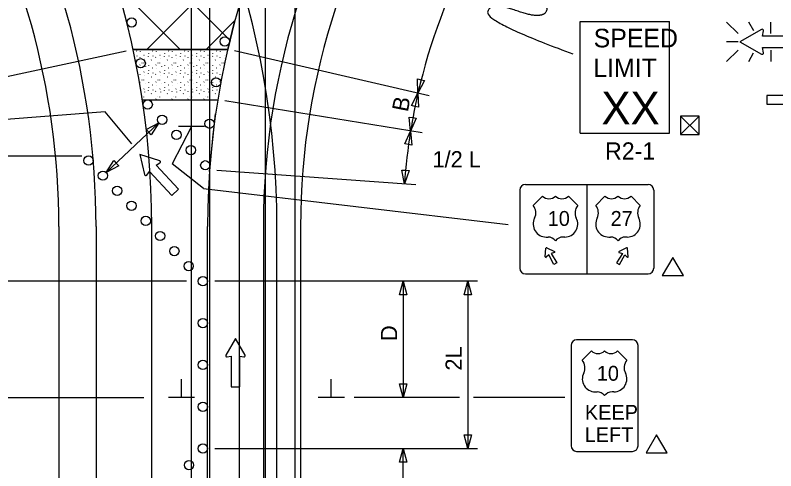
# Model space of a CAD drawing. Extents: x 16452 to 19508, y 5713 to 7079.
# Drawn here: x 16897.2 to 17224.3, y 6278.6 to 6474.6 of the extents above; entities that cross this region are included whole.
import ezdxf

# ---------------------------------------------------------------- set-up
doc = ezdxf.new("R2010")
doc.units = 0
for name, color, linetype in [('ALI_LEGAL_EX', 7, 'Continuous'), ('MT_SCRATCH_LEVEL_A', 7, 'Continuous'), ('MT_SCRATCH_LEVEL_E', 7, 'Continuous'), ('PAVT_EDGE_EX', 7, 'Continuous'), ('TRAFFIC_SIGNS_PR', 7, 'Continuous'), ('TYPICAL_EX', 7, 'Continuous'), ('TYPICAL_TEXT_DIMEN_PR', 7, 'Continuous')]:
    doc.layers.add(name, color=color, linetype=linetype)

msp = doc.modelspace()

# ---------------------------------------------------------------- linework, layer by layer
at = {"layer": 'ALI_LEGAL_EX'}
for p, q in [((16980.68, 6974.12), (16980.68, 6155.98)), ((17004.68, 6974.12), (17004.68, 6155.98)), ((16980.68, 6877.04), (16980.68, 6013.12)), ((17004.68, 6877.04), (17004.68, 6013.12)), ((16973.01, 6139.03), (16973.01, 6639.38)), ((16993.65, 6024.8), (16993.65, 6525.15)), ((17017.65, 6024.8), (17017.65, 6525.15)), ((16955.93, 6107.09), (16955.93, 6383.76)), ((16979.93, 6107.09), (16979.93, 6383.76)), ((17009.75, 5773.57), (17009.75, 6383.76))]:
    msp.add_line(p, q, dxfattribs=at)
for points in [[(16980.7, 6407.3), (16983.32, 6432.16)], [(16955.93, 6307.09), (16955.93, 6332.09)], [(16979.93, 6307.09), (16979.93, 6332.09)]]:
    msp.add_lwpolyline(points, dxfattribs=at)
for centre, radius, start, end in [((16591.93, 6383.76), 364, 0, 40.1909), ((16645.75, 6383.76), 364, 0, 40.1909), ((17319.93, 6383.76), 340, 137.516, 180)]:
    msp.add_arc(centre, radius, start, end, dxfattribs=at)
at = {"layer": 'MT_SCRATCH_LEVEL_A'}
for p, q in [((16953.81, 6459.9), (17004.45, 6510.55)), ((16968.1, 6459.9), (16940.97, 6487.03)), ((16989.56, 6463.9), (16969.88, 6483.58)), ((16979.27, 6459.9), (16991.66, 6472.3)), ((16991.51, 6471.74), (16988.57, 6459.9)), ((16947.88, 6459.9), (16988.57, 6459.9)), ((16947.88, 6459.9), (16988.57, 6459.9)), ((16988.57, 6459.9), (16947.88, 6459.9)), ((16949.38, 6459.26), (16949.43, 6459.18)), ((16950.91, 6459.12), (16950.96, 6459.04)), ((16953.22, 6459.9), (16953.25, 6459.86)), ((16956.26, 6459.26), (16956.31, 6459.18)), ((16957.79, 6459.12), (16957.85, 6459.04)), ((16960.1, 6459.9), (16960.14, 6459.86)), ((16963.15, 6459.26), (16963.2, 6459.18)), ((16964.68, 6459.12), (16964.73, 6459.04)), ((16966.99, 6459.9), (16967.02, 6459.86)), ((16970.04, 6459.26), (16970.09, 6459.18)), ((16971.57, 6459.12), (16971.62, 6459.04)), ((16973.88, 6459.9), (16973.91, 6459.86)), ((16976.93, 6459.26), (16976.98, 6459.18)), ((16978.46, 6459.12), (16978.51, 6459.04)), ((16980.77, 6459.9), (16980.8, 6459.86)), ((16983.81, 6459.26), (16983.87, 6459.18)), ((16985.34, 6459.12), (16985.4, 6459.04)), ((16987.65, 6459.9), (16987.69, 6459.86)), ((16948.81, 6455.3), (16948.86, 6455.41)), ((16949.42, 6457.05), (16949.48, 6456.97)), ((16950.71, 6456.47), (16950.72, 6456.36)), ((16952.55, 6457.33), (16952.6, 6457.44)), ((16952.74, 6456.13), (16952.79, 6456.05)), ((16954.47, 6458.2), (16954.53, 6458.12)), ((16954.52, 6456.8), (16954.57, 6456.91)), ((16955.69, 6455.3), (16955.75, 6455.41)), ((16956.31, 6457.05), (16956.36, 6456.97)), ((16957.59, 6456.47), (16957.61, 6456.36)), ((16959.44, 6457.33), (16959.49, 6457.44)), ((16959.62, 6456.13), (16959.67, 6456.05)), ((16961.36, 6458.2), (16961.41, 6458.12)), ((16961.4, 6456.8), (16961.46, 6456.91)), ((16962.58, 6455.3), (16962.63, 6455.41)), ((16963.2, 6457.05), (16963.25, 6456.97)), ((16964.48, 6456.47), (16964.49, 6456.36)), ((16966.32, 6457.33), (16966.37, 6457.44)), ((16966.51, 6456.13), (16966.56, 6456.05)), ((16968.25, 6458.2), (16968.3, 6458.12)), ((16968.29, 6456.8), (16968.34, 6456.91)), ((16969.47, 6455.3), (16969.52, 6455.41)), ((16970.09, 6457.05), (16970.14, 6456.97)), ((16971.37, 6456.47), (16971.38, 6456.36)), ((16973.21, 6457.33), (16973.26, 6457.44)), ((16973.4, 6456.13), (16973.45, 6456.05)), ((16975.14, 6458.2), (16975.19, 6458.12)), ((16975.18, 6456.8), (16975.23, 6456.91)), ((16976.36, 6455.3), (16976.41, 6455.41)), ((16976.97, 6457.05), (16977.03, 6456.97)), ((16978.26, 6456.47), (16978.27, 6456.36)), ((16980.1, 6457.33), (16980.15, 6457.44)), ((16980.29, 6456.13), (16980.34, 6456.05)), ((16982.02, 6458.2), (16982.08, 6458.12)), ((16982.07, 6456.8), (16982.12, 6456.91)), ((16983.24, 6455.3), (16983.3, 6455.41)), ((16983.86, 6457.05), (16983.91, 6456.97)), ((16985.14, 6456.47), (16985.16, 6456.36)), ((16986.99, 6457.33), (16987.04, 6457.44)), ((16987.17, 6456.13), (16987.22, 6456.05)), ((16950.83, 6453.1), (16950.88, 6453.22)), ((16951.59, 6454.06), (16951.64, 6453.98)), ((16952.33, 6454.03), (16952.38, 6453.95)), ((16953.2, 6452.65), (16953.25, 6452.57)), ((16954.65, 6452.8), (16954.7, 6452.92)), ((16956.26, 6451.97), (16956.31, 6451.9)), ((16957.71, 6453.1), (16957.76, 6453.22)), ((16958.48, 6454.06), (16958.53, 6453.98)), ((16959.22, 6454.03), (16959.27, 6453.95)), ((16960.08, 6452.65), (16960.14, 6452.57)), ((16961.53, 6452.8), (16961.58, 6452.92)), ((16963.15, 6451.97), (16963.2, 6451.9)), ((16964.6, 6453.1), (16964.65, 6453.22)), ((16965.37, 6454.06), (16965.42, 6453.98)), ((16966.1, 6454.03), (16966.15, 6453.95)), ((16966.97, 6452.65), (16967.02, 6452.57)), ((16968.42, 6452.8), (16968.47, 6452.92)), ((16970.04, 6451.97), (16970.09, 6451.9)), ((16971.49, 6453.1), (16971.54, 6453.22)), ((16972.25, 6454.06), (16972.3, 6453.98)), ((16972.99, 6454.03), (16973.04, 6453.95)), ((16973.86, 6452.65), (16973.91, 6452.57)), ((16975.31, 6452.8), (16975.36, 6452.92)), ((16976.93, 6451.97), (16976.98, 6451.9)), ((16978.38, 6453.1), (16978.43, 6453.22)), ((16979.14, 6454.06), (16979.19, 6453.98)), ((16979.88, 6454.03), (16979.93, 6453.95)), ((16980.75, 6452.65), (16980.8, 6452.57)), ((16982.19, 6452.8), (16982.25, 6452.92)), ((16983.81, 6451.97), (16983.87, 6451.9)), ((16985.26, 6453.1), (16985.31, 6453.22)), ((16986.03, 6454.06), (16986.08, 6453.98)), ((16986.76, 6454.03), (16986.82, 6453.95)), ((16950.71, 6449.19), (16950.72, 6449.07)), ((16950.91, 6451.83), (16950.96, 6451.76)), ((16952.55, 6450.04), (16952.6, 6450.16)), ((16952.74, 6448.85), (16952.79, 6448.77)), ((16954.47, 6450.91), (16954.53, 6450.84)), ((16954.52, 6449.51), (16954.57, 6449.63)), ((16956.31, 6449.76), (16956.36, 6449.69)), ((16957.59, 6449.19), (16957.61, 6449.07)), ((16957.79, 6451.83), (16957.85, 6451.76)), ((16959.44, 6450.04), (16959.49, 6450.16)), ((16959.62, 6448.85), (16959.67, 6448.77)), ((16961.36, 6450.91), (16961.41, 6450.84)), ((16961.4, 6449.51), (16961.46, 6449.63)), ((16963.2, 6449.76), (16963.25, 6449.69)), ((16964.48, 6449.19), (16964.49, 6449.07)), ((16964.68, 6451.83), (16964.73, 6451.76)), ((16966.32, 6450.04), (16966.37, 6450.16)), ((16966.51, 6448.85), (16966.56, 6448.77)), ((16968.25, 6450.91), (16968.3, 6450.84)), ((16968.29, 6449.51), (16968.34, 6449.63)), ((16970.09, 6449.76), (16970.14, 6449.69)), ((16971.37, 6449.19), (16971.38, 6449.07)), ((16971.57, 6451.83), (16971.62, 6451.76)), ((16973.21, 6450.04), (16973.26, 6450.16)), ((16973.4, 6448.85), (16973.45, 6448.77)), ((16975.14, 6450.91), (16975.19, 6450.84)), ((16975.18, 6449.51), (16975.23, 6449.63)), ((16976.97, 6449.76), (16977.03, 6449.69)), ((16978.26, 6449.19), (16978.27, 6449.07)), ((16978.46, 6451.83), (16978.51, 6451.76)), ((16980.1, 6450.04), (16980.15, 6450.16)), ((16980.29, 6448.85), (16980.34, 6448.77)), ((16982.02, 6450.91), (16982.08, 6450.84)), ((16982.07, 6449.51), (16982.12, 6449.63)), ((16983.86, 6449.76), (16983.91, 6449.69)), ((16985.14, 6449.19), (16985.16, 6449.07)), ((16985.34, 6451.83), (16985.4, 6451.76)), ((16950.83, 6445.82), (16950.88, 6445.93)), ((16951.59, 6446.78), (16951.64, 6446.7)), ((16952.33, 6446.74), (16952.38, 6446.67)), ((16953.2, 6445.37), (16953.25, 6445.29)), ((16954.65, 6445.52), (16954.7, 6445.63)), ((16955.69, 6448.01), (16955.75, 6448.13)), ((16957.71, 6445.82), (16957.76, 6445.93)), ((16958.48, 6446.78), (16958.53, 6446.7)), ((16959.22, 6446.74), (16959.27, 6446.67)), ((16960.08, 6445.37), (16960.14, 6445.29)), ((16961.53, 6445.52), (16961.58, 6445.63)), ((16962.58, 6448.01), (16962.63, 6448.13)), ((16964.6, 6445.82), (16964.65, 6445.93)), ((16965.37, 6446.78), (16965.42, 6446.7)), ((16966.1, 6446.74), (16966.15, 6446.67)), ((16966.97, 6445.37), (16967.02, 6445.29)), ((16968.42, 6445.52), (16968.47, 6445.63)), ((16969.47, 6448.01), (16969.52, 6448.13)), ((16971.49, 6445.82), (16971.54, 6445.93)), ((16972.25, 6446.78), (16972.3, 6446.7)), ((16972.99, 6446.74), (16973.04, 6446.67)), ((16973.86, 6445.37), (16973.91, 6445.29)), ((16975.31, 6445.52), (16975.36, 6445.63)), ((16976.36, 6448.01), (16976.41, 6448.13)), ((16978.38, 6445.82), (16978.43, 6445.93)), ((16979.14, 6446.78), (16979.19, 6446.7)), ((16979.88, 6446.74), (16979.93, 6446.67)), ((16980.75, 6445.37), (16980.8, 6445.29)), ((16982.19, 6445.52), (16982.25, 6445.63)), ((16983.24, 6448.01), (16983.3, 6448.13)), ((16985.26, 6445.82), (16985.31, 6445.93)), ((16950.91, 6444.55), (16950.96, 6444.47)), ((16952.55, 6442.76), (16952.6, 6442.88)), ((16954.47, 6443.63), (16954.53, 6443.55)), ((16954.52, 6442.23), (16954.57, 6442.35)), ((16956.26, 6444.69), (16956.31, 6444.61)), ((16956.31, 6442.48), (16956.36, 6442.4)), ((16957.79, 6444.55), (16957.85, 6444.47)), ((16959.44, 6442.76), (16959.49, 6442.88)), ((16961.36, 6443.63), (16961.41, 6443.55)), ((16961.4, 6442.23), (16961.46, 6442.35)), ((16963.15, 6444.69), (16963.2, 6444.61)), ((16963.2, 6442.48), (16963.25, 6442.4)), ((16964.68, 6444.55), (16964.73, 6444.47)), ((16966.32, 6442.76), (16966.37, 6442.88)), ((16968.25, 6443.63), (16968.3, 6443.55)), ((16968.29, 6442.23), (16968.34, 6442.35)), ((16970.04, 6444.69), (16970.09, 6444.61)), ((16970.09, 6442.48), (16970.14, 6442.4)), ((16971.57, 6444.55), (16971.62, 6444.47)), ((16973.21, 6442.76), (16973.26, 6442.88)), ((16975.14, 6443.63), (16975.19, 6443.55)), ((16975.18, 6442.23), (16975.23, 6442.35)), ((16976.93, 6444.69), (16976.98, 6444.61)), ((16976.97, 6442.48), (16977.03, 6442.4)), ((16978.46, 6444.55), (16978.51, 6444.47)), ((16980.1, 6442.76), (16980.15, 6442.88)), ((16982.02, 6443.63), (16982.08, 6443.55)), ((16982.07, 6442.23), (16982.12, 6442.35)), ((16983.81, 6444.69), (16983.87, 6444.61)), ((16983.86, 6442.48), (16983.91, 6442.4)), ((16985.34, 6444.55), (16985.4, 6444.47)), ((16951.64, 6439.41), (16951.64, 6439.41)), ((16952.33, 6439.46), (16952.38, 6439.38)), ((16952.74, 6441.56), (16952.79, 6441.48)), ((16955.69, 6440.73), (16955.75, 6440.84)), ((16957.59, 6441.9), (16957.61, 6441.79)), ((16958.48, 6439.49), (16958.53, 6439.41)), ((16959.22, 6439.46), (16959.27, 6439.38)), ((16959.62, 6441.56), (16959.67, 6441.48)), ((16962.58, 6440.73), (16962.63, 6440.84)), ((16964.48, 6441.9), (16964.49, 6441.79)), ((16965.37, 6439.49), (16965.42, 6439.41)), ((16966.1, 6439.46), (16966.15, 6439.38)), ((16966.51, 6441.56), (16966.56, 6441.48)), ((16969.47, 6440.73), (16969.52, 6440.84)), ((16971.37, 6441.9), (16971.38, 6441.79)), ((16972.25, 6439.49), (16972.3, 6439.41)), ((16972.99, 6439.46), (16973.04, 6439.38)), ((16973.4, 6441.56), (16973.45, 6441.48)), ((16976.36, 6440.73), (16976.41, 6440.84)), ((16978.26, 6441.9), (16978.27, 6441.79)), ((16979.14, 6439.49), (16979.19, 6439.41)), ((16979.88, 6439.46), (16979.93, 6439.38)), ((16980.29, 6441.56), (16980.34, 6441.48)), ((16983.24, 6440.73), (16983.3, 6440.84)), ((16951.84, 6438.16), (16984.31, 6438.16)), ((16951.84, 6438.16), (16984.31, 6438.16)), ((16954.65, 6438.23), (16954.7, 6438.35)), ((16957.71, 6438.53), (16957.76, 6438.65)), ((16961.53, 6438.23), (16961.58, 6438.35)), ((16964.6, 6438.53), (16964.65, 6438.65)), ((16968.42, 6438.23), (16968.47, 6438.35)), ((16971.49, 6438.53), (16971.54, 6438.65)), ((16975.31, 6438.23), (16975.36, 6438.35)), ((16978.38, 6438.53), (16978.43, 6438.65)), ((16982.19, 6438.23), (16982.25, 6438.35))]:
    msp.add_line(p, q, dxfattribs=at)
msp.add_lwpolyline([(16947.88, 6459.9), (16988.57, 6459.9), (16991.51, 6471.74)], dxfattribs=at)
at = {"layer": 'MT_SCRATCH_LEVEL_E'}
for p, q in [((17233.72, 6440.1), (17220.46, 6440.1)), ((17220.46, 6440.1), (17220.46, 6436.36)), ((17220.46, 6436.36), (17233.72, 6436.36)), ((16991.9, 6335.57), (16987.79, 6328.32)), ((16996.05, 6328.32), (16991.9, 6335.57)), ((16988.27, 6327.64), (16990.05, 6327.96)), ((16990.05, 6327.96), (16990.05, 6314.7)), ((16993.79, 6314.7), (16993.79, 6327.96)), ((16993.79, 6327.96), (16995.57, 6327.64)), ((16990.05, 6314.7), (16993.79, 6314.7))]:
    msp.add_line(p, q, dxfattribs=at)
for centre, start, end in [((16988.2, 6328.1), 150.4248, 279.9638), ((16995.64, 6328.1), 260.0362, 29.7731)]:
    msp.add_arc(centre, 0.463, start, end, dxfattribs=at)
at = {"layer": 'PAVT_EDGE_EX'}
for p, q in [((16915.93, 6383.76), (16915.93, 6107.09)), ((16931.93, 6383.76), (16931.93, 6107.09)), ((17003.93, 6383.76), (17003.93, 6107.09)), ((17019.93, 6383.76), (17019.93, 6107.09))]:
    msp.add_line(p, q, dxfattribs=at)
for centre, radius, start, end in [((17319.93, 6383.76), 316, 107.923, 180), ((16591.93, 6383.76), 340, 0, 61.4862), ((16591.93, 6383.76), 324, 0, 61.4862), ((17319.93, 6383.76), 300, 107.923, 180), ((17319.93, 6383.76), 300, 180, 180.00000277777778)]:
    msp.add_arc(centre, radius, start, end, dxfattribs=at)
at = {"layer": 'TRAFFIC_SIGNS_PR'}
for p, q in [((17140.23, 6471.88), (17178.63, 6471.88)), ((17140.23, 6423.88), (17140.23, 6471.88)), ((17178.63, 6423.88), (17178.63, 6471.88)), ((17203.18, 6471.64), (17208.11, 6466.71)), ((17214.94, 6467.82), (17212.74, 6471.65)), ((17222.26, 6466.71), (17222.26, 6471.65)), ((17208.11, 6463.15), (17203.18, 6463.15)), ((17203.18, 6454.67), (17208.11, 6459.6)), ((17222.26, 6459.6), (17222.26, 6454.66)), ((17212.69, 6454.66), (17214.8, 6458.33)), ((17140.23, 6423.88), (17178.63, 6423.88)), ((17116.62, 6401.76), (17169.42, 6401.76)), ((17143.02, 6401.76), (17143.02, 6363.36)), ((17114.22, 6399.36), (17114.22, 6365.76)), ((17171.82, 6399.36), (17171.82, 6365.76)), ((17125.2, 6370.71), (17125.48, 6374.33)), ((17125.86, 6374.54), (17129.13, 6372.98)), ((17160.19, 6374.54), (17156.91, 6372.98)), ((17160.84, 6370.71), (17160.56, 6374.33)), ((17116.62, 6363.36), (17169.42, 6363.36)), ((17162.69, 6334.97), (17138.69, 6334.97)), ((17136.3, 6332.57), (17136.3, 6289.36)), ((17165.1, 6289.36), (17165.1, 6332.57)), ((17138.69, 6286.97), (17162.69, 6286.97))]:
    msp.add_line(p, q, dxfattribs=at)
for points in [[(17218.19, 6468.43), (17208.9, 6463.15), (17218.19, 6457.83)], [(17219.06, 6458.46), (17218.66, 6460.73), (17235.68, 6460.73), (17235.68, 6465.53), (17218.66, 6465.53), (17219.07, 6467.81)], [(17129.09, 6372.49), (17127.69, 6372.1), (17130.2, 6368.12), (17128.87, 6367.36), (17126.68, 6371.53), (17125.64, 6370.5)], [(17156.95, 6372.49), (17158.36, 6372.1), (17155.84, 6368.12), (17157.17, 6367.36), (17159.36, 6371.53), (17160.4, 6370.5)]]:
    msp.add_lwpolyline(points, dxfattribs=at)
for centre in [(16947.27, 6471.47), (16987.31, 6463.31), (16951.15, 6453.9), (16983.59, 6445.7), (16954.16, 6436.15), (16954.16, 6436.15), (16954.16, 6436.15), (16960.35, 6429.62), (16980.79, 6427.92), (16966.54, 6423.09), (16972.74, 6416.56), (16928.74, 6412.06), (16978.94, 6410.02), (16934.89, 6405.57), (16941.04, 6399.08), (16947.19, 6392.6), (16953.34, 6386.11), (16959.48, 6379.62), (16965.63, 6373.14), (16971.78, 6366.65), (16977.93, 6360.16), (16977.93, 6360.16), (16977.93, 6342.16), (16977.93, 6324.16), (16977.93, 6306.16), (16977.93, 6288.21), (16971.93, 6281.07)]:
    msp.add_circle(centre, 2, dxfattribs=at)
for centre, radius, start, end in [((17218.48, 6467.91), 0.598, 350.7308, 118.8916), ((17218.48, 6458.36), 0.597, 241.4833, 9.9593), ((17116.62, 6399.36), 2.4, 90, 180), ((17116.62, 6399.36), 2.4, 90, 180), ((17169.42, 6399.36), 2.4, 0, 90), ((17125.74, 6374.31), 0.26, 64.4823, 175.5177), ((17160.3, 6374.31), 0.26, 4.4823, 115.5177), ((17125.46, 6370.69), 0.26, 175.5177, 314.0115), ((17129.02, 6372.74), 0.26, 285.9885, 64.4823), ((17157.02, 6372.74), 0.26, 115.5177, 254.0115), ((17160.58, 6370.69), 0.26, 225.9885, 4.4823), ((17116.62, 6365.76), 2.4, 180, 270), ((17169.42, 6365.76), 2.4, 270, 0), ((17138.69, 6332.57), 2.4, 90, 180), ((17162.69, 6332.57), 2.4, 0, 90), ((17138.69, 6289.37), 2.4, 180, 270), ((17162.69, 6289.37), 2.4, 270, 0)]:
    msp.add_arc(centre, radius, start, end, dxfattribs=at)
at = {"layer": 'TYPICAL_EX'}
for p, q in [((17119.97, 6392.76), (17123.97, 6396.76)), ((17139.17, 6392.76), (17135.17, 6396.76)), ((17146.87, 6392.76), (17150.87, 6396.76)), ((17166.07, 6392.76), (17162.07, 6396.76)), ((17125.57, 6379.15), (17126.37, 6379.15)), ((17133.58, 6379.15), (17132.78, 6379.15)), ((17152.47, 6379.15), (17153.27, 6379.15)), ((17160.48, 6379.15), (17159.68, 6379.15)), ((17141.1, 6326.17), (17145.1, 6330.17)), ((17160.3, 6326.17), (17156.3, 6330.17)), ((17146.69, 6312.56), (17147.49, 6312.56)), ((17154.7, 6312.56), (17153.9, 6312.56))]:
    msp.add_line(p, q, dxfattribs=at)
for centre, radius, start, end in [((17126.77, 6399.67), 4.04, 226.1404, 313.8596), ((17132.37, 6399.67), 4.04, 226.1404, 313.8596), ((17153.67, 6399.67), 4.04, 226.1404, 313.8596), ((17159.27, 6399.67), 4.04, 226.1404, 313.8596), ((17116.18, 6389.55), 4.96, 333.0977, 40.1936), ((17142.96, 6389.55), 4.96, 139.8064, 206.9023), ((17143.08, 6389.55), 4.96, 333.0977, 40.1936), ((17169.86, 6389.55), 4.96, 139.8064, 206.9023), ((17125.58, 6384.74), 5.59, 152.6698, 269.9013), ((17133.57, 6384.74), 5.59, 270.0987, 27.3302), ((17152.48, 6384.74), 5.59, 152.6698, 269.9013), ((17160.47, 6384.74), 5.59, 270.0987, 27.3302), ((17126.38, 6375.14), 4.01, 37.1038, 90.1385), ((17132.77, 6375.14), 4.01, 89.8615, 142.8962), ((17153.28, 6375.14), 4.01, 37.1038, 90.1385), ((17159.67, 6375.14), 4.01, 89.8615, 142.8962), ((17147.89, 6333.08), 4.04, 226.1404, 313.8596), ((17153.49, 6333.08), 4.04, 226.1404, 313.8596), ((17137.3, 6322.96), 4.96, 333.0977, 40.1936), ((17164.08, 6322.96), 4.96, 139.8064, 206.9023), ((17146.7, 6318.15), 5.59, 152.6698, 269.9013), ((17154.69, 6318.15), 5.59, 270.0987, 27.3302), ((17147.5, 6308.55), 4.01, 37.1038, 90.1385), ((17153.89, 6308.55), 4.01, 89.8615, 142.8962)]:
    msp.add_arc(centre, radius, start, end, dxfattribs=at)
at = {"layer": 'TYPICAL_TEXT_DIMEN_PR'}
for p, q in [((16860.85, 6441.29), (16944.94, 6459.28)), ((17075.31, 6439.97), (16991.54, 6459.22)), ((17070.43, 6441.09), (17070.22, 6447.16)), ((17070.22, 6447.16), (17071.75, 6446.81)), ((17073.28, 6446.45), (17070.43, 6441.09)), ((17071.75, 6446.81), (17073.28, 6446.45)), ((17067.59, 6435.73), (17070.43, 6441.09)), ((17070.43, 6441.09), (17070.65, 6435.03)), ((17072.17, 6423.92), (16987.32, 6437.68)), ((17069.12, 6435.38), (17067.59, 6435.73)), ((16935.91, 6433.02), (16850.71, 6426.47)), ((16947.27, 6419.32), (16935.91, 6433.02)), ((16973.04, 6426.65), (16973.04, 6434.44)), ((17070.65, 6435.03), (17069.12, 6435.38)), ((17067.23, 6424.72), (17066.62, 6430.76)), ((17066.62, 6430.76), (17068.17, 6430.51)), ((17067.23, 6424.72), (17066.62, 6430.76)), ((17066.62, 6430.76), (17068.17, 6430.51)), ((17069.72, 6430.26), (17067.23, 6424.72)), ((17069.72, 6430.26), (17067.23, 6424.72)), ((17068.17, 6430.51), (17069.72, 6430.26)), ((17068.17, 6430.51), (17069.72, 6430.26)), ((17183.42, 6431.2), (17191.42, 6423.2)), ((17183.42, 6423.2), (17191.42, 6431.2)), ((16958.9, 6428.25), (16936.35, 6406.94)), ((16953.56, 6425.36), (16958.9, 6428.25)), ((16958.9, 6428.25), (16955.72, 6423.08)), ((16973.04, 6426.65), (16964.73, 6410.68)), ((16978.66, 6426.65), (16967.41, 6426.65)), ((16954.64, 6424.22), (16953.56, 6425.36)), ((16955.72, 6423.08), (16954.64, 6424.22)), ((17064.74, 6419.19), (17067.23, 6424.72)), ((17067.23, 6424.72), (17067.84, 6418.69)), ((17066.29, 6418.94), (17064.74, 6419.19)), ((17067.84, 6418.69), (17066.29, 6418.94)), ((16865.26, 6414.06), (16925.83, 6414.06)), ((16959.32, 6412), (16950.83, 6414.66)), ((16950.83, 6414.66), (16952.85, 6406.02)), ((16936.35, 6406.94), (16939.53, 6412.11)), ((16941.69, 6409.83), (16936.35, 6406.94)), ((16939.53, 6412.11), (16940.61, 6410.97)), ((16940.61, 6410.97), (16941.69, 6409.83)), ((16957.82, 6410.08), (16959.44, 6411.12)), ((16967.43, 6399.7), (16957.82, 6410.08)), ((16978.14, 6399.98), (16964.73, 6410.68)), ((16953.73, 6405.83), (16954.89, 6407.37)), ((16954.89, 6407.37), (16964.5, 6396.99)), ((17069.57, 6401.67), (16983.84, 6407.81)), ((17064.58, 6402.03), (17063.44, 6407.99)), ((17063.44, 6407.99), (17065, 6407.88)), ((17066.57, 6407.76), (17064.58, 6402.03)), ((17065, 6407.88), (17066.57, 6407.76)), ((16964.5, 6396.99), (16967.43, 6399.7)), ((16978.14, 6399.98), (17109.28, 6384.63)), ((16970.82, 6360.21), (16866.93, 6360.21)), ((17096.07, 6360.21), (16982.98, 6360.21)), ((17062.46, 6354.35), (17064.03, 6360.21)), ((17064.03, 6360.21), (17065.6, 6354.35)), ((17064.03, 6360.21), (17064.03, 6310.21)), ((17090.26, 6354.35), (17091.83, 6360.21)), ((17091.83, 6360.21), (17091.83, 6288.21)), ((17091.83, 6360.21), (17093.4, 6354.35)), ((17064.03, 6354.35), (17062.46, 6354.35)), ((17065.6, 6354.35), (17064.03, 6354.35)), ((17091.83, 6354.35), (17090.26, 6354.35)), ((17093.4, 6354.35), (17091.83, 6354.35)), ((16968.68, 6310.21), (16968.68, 6318)), ((17033.15, 6310.21), (17033.15, 6318)), ((17064.03, 6310.21), (17062.46, 6316.07)), ((17062.46, 6316.07), (17064.03, 6316.07)), ((17064.03, 6316.07), (17065.6, 6316.07)), ((17065.6, 6316.07), (17064.03, 6310.21)), ((16867.03, 6310.21), (16952.43, 6310.21)), ((16974.31, 6310.21), (16963.06, 6310.21)), ((17038.78, 6310.21), (17027.53, 6310.21)), ((17088.3, 6310.21), (17043.03, 6310.21)), ((17133.57, 6310.21), (17094.37, 6310.21)), ((17091.83, 6288.21), (17090.26, 6294.07)), ((17090.26, 6294.07), (17091.83, 6294.07)), ((17091.83, 6294.07), (17093.4, 6294.07)), ((17093.4, 6294.07), (17091.83, 6288.21)), ((16982.98, 6288.21), (17096.07, 6288.21)), ((17062.46, 6282.35), (17064.03, 6288.21)), ((17064.03, 6259.65), (17064.03, 6288.21)), ((17064.03, 6288.21), (17065.6, 6282.35)), ((17064.03, 6282.35), (17062.46, 6282.35)), ((17065.6, 6282.35), (17064.03, 6282.35))]:
    msp.add_line(p, q, dxfattribs=at)
for points in [[(17183.42, 6431.2), (17183.42, 6423.2), (17191.42, 6423.2), (17191.42, 6431.2)], [(17180.05, 6370.43), (17175.53, 6362.59), (17184.58, 6362.59)], [(17173.06, 6294.14), (17168.54, 6286.31), (17177.59, 6286.31)]]:
    msp.add_lwpolyline(points, close=True, dxfattribs=at)
for centre, radius, start, end in [((17319.93, 6383.76), 256, 137.0843, 167.0592), ((17319.93, 6383.76), 256, 167.0592, 170.7929), ((17319.93, 6383.76), 256, 170.7929, 175.9084), ((16959.16, 6411.53), 0.494, 302.8238, 72.5607), ((16953.34, 6406.14), 0.494, 193.2124, 322.7514)]:
    msp.add_arc(centre, radius, start, end, dxfattribs=at)
msp.add_open_spline([(17095.73, 6492.44), (17127.37, 6480.93), (17124.25, 6472.36), (17101.95, 6480.48), (17098.84, 6471.91), (17137.06, 6458)], degree=2, dxfattribs=at)

# ---------------------------------------------------------------- texts
at = {"layer": 'TRAFFIC_SIGNS_PR'}
for s, height, p in [('SPEED', 8, (17146, 6460.74)), ('LIMIT', 8, (17145.84, 6447.94)), ('XX', 14.031, (17149.35, 6427.64)), ('R2-1', 7.44, (17150.91, 6412.44)), ('10', 6.4, (17126.23, 6383.96)), ('27', 6.4, (17153.3, 6383.96)), ('10', 6.4, (17147.35, 6317.36)), ('KEEP', 6.4, (17142.23, 6300.57)), ('LEFT', 6.4, (17142.14, 6290.97))]:
    msp.add_text(s, height=height, dxfattribs=at).set_placement(p)
at = {"layer": 'TYPICAL_TEXT_DIMEN_PR'}
for s, rotation, p in [('B', 78.9226, (17066.04, 6432.68)), ('D', 90, (17061.47, 6334.43)), ('2L', 90, (17089.28, 6321.72))]:
    msp.add_text(s, height=7, rotation=rotation, dxfattribs=at).set_placement(p)
msp.add_text('1/2 L', height=7, dxfattribs=at).set_placement((17076.67, 6409.1))

doc.saveas('drawing.dxf')
